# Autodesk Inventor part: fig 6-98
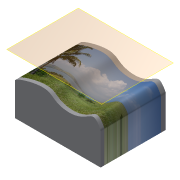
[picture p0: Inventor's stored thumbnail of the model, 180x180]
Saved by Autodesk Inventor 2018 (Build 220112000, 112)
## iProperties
Created: 2012-07
Part Number: fig 6-98
Material: Generic
Document SubType Name: Modeling
Designer: CADCIM
Density: 1 g/cm^3
Appearance: Default
Author: CADCIM
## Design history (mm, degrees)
sketch "Sketch1"
  geometry: L1 (0, 0)-(0, 12.146); L2 (32.23, 12.146)-(32.23, 0); L3 (32.23, 0)-(0, 0); 5 further points
  constraints: 6 end point, 1 parallel, 1 perpendicular, 1 vertical, 7 other
extrude "Extrusion1" new body sketch "Sketch1" distance "d0" = 24.5; taper "d1" = 0 deg
workplane "Work Plane1"
fillet "Fillet1" dims "d19" = 2
sketch "Sketch2"
  geometry: L1 (-33.343, 22.666)-(0.669, 22.666); L2 (0.669, 22.666)-(0.669, 1.409); L3 (0.669, 1.409)-(-33.343, 1.409); L4 (-33.343, 1.409)-(-33.343, 22.666); 1 other entity
  constraints: 2 other
feature "Decal1" sketch "Sketch2"
body "Solid1"
node "Image1"
other parameters: "d2" = 22
